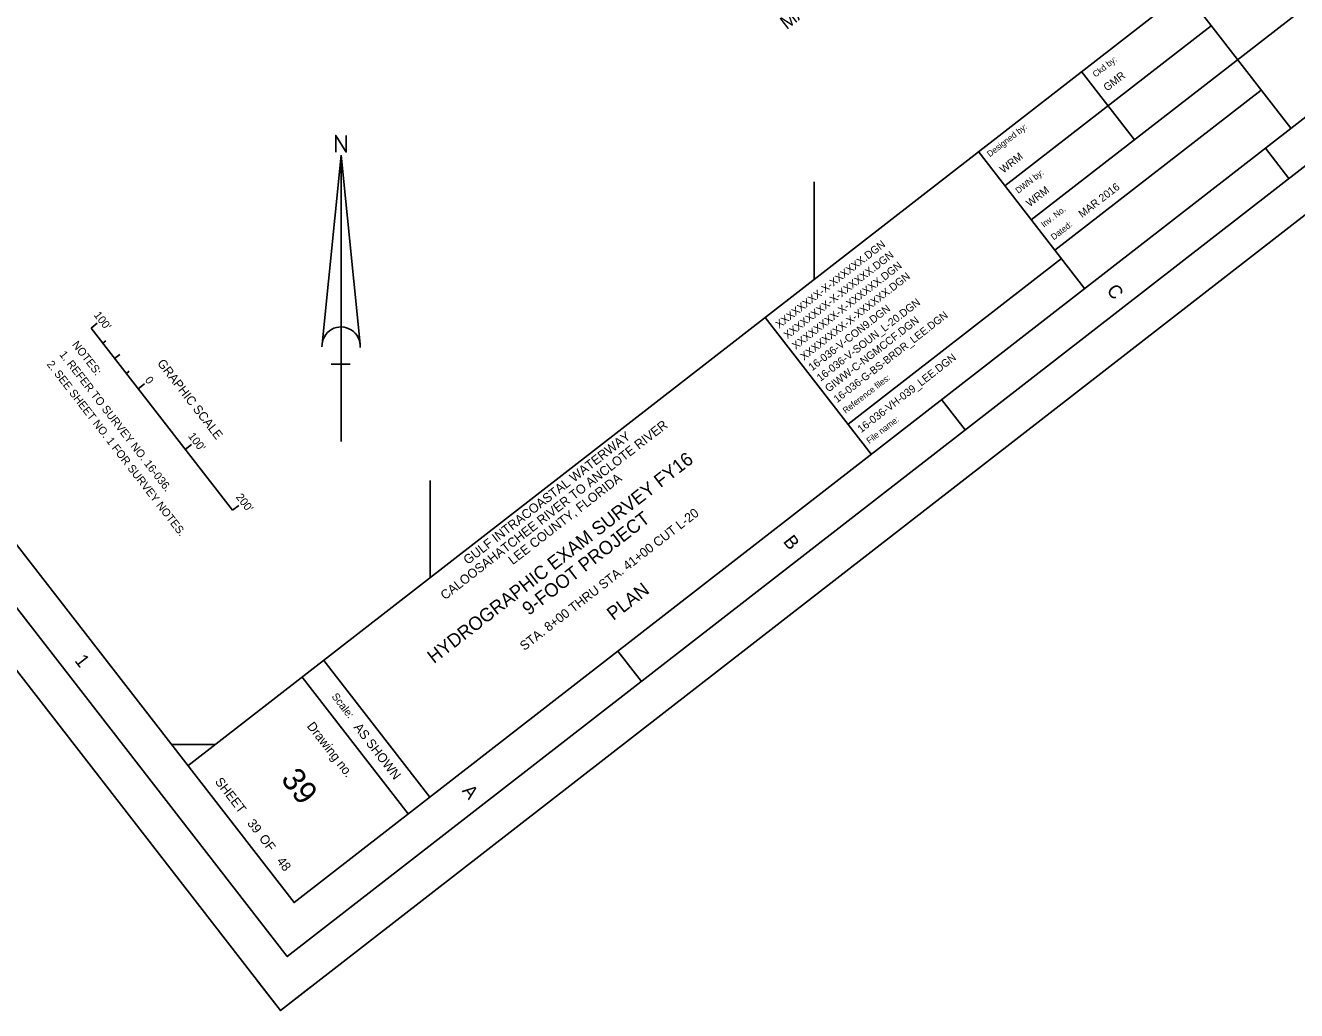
# Model space of a CAD drawing. Extents: x 577607 to 582991, y 855154 to 860715.
# Drawn here: x 579974 to 581627, y 855154 to 856435 of the extents above; entities that cross this region are included whole.
import ezdxf

# ---------------------------------------------------------------- set-up
doc = ezdxf.new("R2010")
doc.units = 0
for name, color, linetype in [('G-ANNO-NPLT', 7, 'Continuous'), ('G-ANNO-TEXT-DRWG', 7, 'Continuous'), ('G-ANNO-TEXT-PROJ', 7, 'Continuous'), ('G-ANNO-TEXT-TTLB', 7, 'Continuous'), ('G-ANNO-TTLB', 7, 'Continuous'), ('V-ANNO-MATC-IDEN', 7, 'Continuous'), ('V-ANNO-NOTE', 7, 'Continuous'), ('V-ANNO-SYMB', 7, 'Continuous'), ('V-TOPO-COOR-STAT', 7, 'Continuous')]:
    doc.layers.add(name, color=color, linetype=linetype)

msp = doc.modelspace()

# ---------------------------------------------------------------- linework, layer by layer
at = {"layer": 'G-ANNO-NPLT'}
msp.add_lwpolyline([(580293.3, 860714.9), (582991.2, 857239.1), (580305.4, 855154.4), (577607.4, 858630.1)], close=True, dxfattribs=at)
msp.add_lwpolyline([(580345, 855184.9), (580305.5, 855154.3), (580274.8, 855193.8)], dxfattribs=at)
at = {"layer": 'G-ANNO-TTLB'}
for p, q in [((582712.9, 857434.6), (580185.1, 855472.4)), ((581282.3, 856182.5), (581961.7, 856709)), ((581481.6, 856479.8), (581620, 856301.4)), ((581248, 856226.7), (581516.5, 856434.8)), ((581347.4, 856375.6), (581416.5, 856286.5)), ((581581.4, 856351.1), (581313.1, 856142.9)), ((581617.5, 856236.2), (581586.9, 856275.7)), ((581213, 856271.8), (581351.7, 856093.1)), ((581321.5, 856132.1), (581043.9, 855916.6)), ((580936.1, 856055.4), (581074.1, 855877.7)), ((581196.3, 855909.2), (581165.6, 855948.7)), ((580775, 855582.2), (580744.3, 855621.7)), ((580361.8, 855609.6), (580499.8, 855431.9)), ((580333.6, 855587.8), (580471.6, 855410))]:
    msp.add_line(p, q, dxfattribs=at)
for points in [[(577677.6, 858621.3), (580314.2, 855224.5), (582921, 857248), (580284.4, 860644.7)], [(582850.9, 857256.8), (580321.6, 860515.3), (577793.7, 858553.2), (580323.1, 855294.7)]]:
    msp.add_lwpolyline(points, close=True, dxfattribs=at)
at = {"layer": 'V-ANNO-NOTE'}
for p, q in [((580058.9, 856041.7), (580067.1, 856048.1)), ((580058.9, 856041.7), (580242.8, 855804.7)), ((580074.2, 856021.9), (580078, 856024.9)), ((580089.5, 856002.2), (580096.3, 856007.4)), ((580104.9, 855982.4), (580108.6, 855985.4)), ((580120.2, 855962.7), (580128.4, 855969.1)), ((580120.2, 855962.7), (580128.4, 855969.1)), ((580120.2, 855962.7), (580124.1, 855965.7)), ((580181.5, 855883.7), (580189.8, 855890.1)), ((580242.8, 855804.7), (580251.1, 855811.1))]:
    msp.add_line(p, q, dxfattribs=at)
at = {"layer": 'V-ANNO-SYMB'}
for p, q in [((580359.6, 856020.8), (580384.2, 856266.5)), ((580384.2, 855894.2), (580384.2, 856266.5)), ((580408.9, 856020.8), (580384.2, 856266.5)), ((580396, 855994.7), (580371.2, 855994.7))]:
    msp.add_line(p, q, dxfattribs=at)
msp.add_lwpolyline([(580377.4, 856270.5), (580377.4, 856292.2), (580390.9, 856270.5), (580390.9, 856292.2)], dxfattribs=at)
msp.add_arc((580384.2, 856018.3), 24.8, 355.2984, 182.0673, dxfattribs=at)
at = {"layer": 'V-TOPO-COOR-STAT'}
for p, q in [((581000, 856105), (581000, 856231.6)), ((580500, 855716.9), (580500, 855843.5)), ((580163.7, 855500), (580220.6, 855500))]:
    msp.add_line(p, q, dxfattribs=at)

# ---------------------------------------------------------------- texts
at = {"layer": 'G-ANNO-TEXT-DRWG'}
for s, height, rotation, p in [('GMR', 10, 37.8192, (581381, 856349.1)), ('WRM', 10, 37.8192, (581246, 856242.4)), ('WRM', 10, 37.8192, (581280.3, 856198.6)), ('XXXXXXXX-X-XXXXXX.DGN', 10, 37.8192, (580954.3, 856040.7)), ('XXXXXXXX-X-XXXXXX.DGN', 10, 37.8192, (580965.1, 856026.9)), ('XXXXXXXX-X-XXXXXX.DGN', 10, 37.8192, (580975.8, 856013.1)), ('XXXXXXXX-X-XXXXXX.DGN', 10, 37.8192, (580986.5, 855999.2)), ('16-036-V-SOUN_L-20.DGN', 10, 37.8192, (581008, 855971.6)), ('16-036-V-CON9.DGN', 10, 37.8192, (580997.2, 855985.4)), ('GIWW-C-NGMCCF.DGN', 10, 37.8192, (581018.7, 855957.8)), ('16-036-VH-039_LEE.DGN', 10, 37.8192, (581061, 855904.9)), ('STA. 8+00 THRU STA. 41+00 CUT L-20', 12, 37.8192, (580622.7, 855621.7)), ('PLAN', 17.5, 37.8192, (580738.6, 855660.8)), ('39', 30, 307.8192, (580304.9, 855454.8)), (' 39          48', 12, 307.8192, (580258.8, 855401.1))]:
    msp.add_text(s, height=height, rotation=rotation, dxfattribs=at).set_placement(p)
at = {"layer": 'G-ANNO-TEXT-PROJ'}
for s, height, p in [('MAR 2016', 10, (581348.5, 856184.6)), ('16-036-G-BS-BRDR_LEE.DGN', 9.8, (581029.8, 855944)), ('CALOOSAHATCHEE RIVER TO ANCLOTE RIVER', 12, (580519.5, 855687.6)), ('GULF INTRACOASTAL WATERWAY', 12, (580549.2, 855733.5)), ('HYDROGRAPHIC EXAM SURVEY FY16', 17.5, (580505.1, 855604.7)), ('LEE COUNTY, FLORIDA', 12, (580607.7, 855733.3)), ('9-FOOT PROJECT', 17.5, (580628.5, 855667.2))]:
    msp.add_text(s, height=height, rotation=37.8192, dxfattribs=at).set_placement(p)
at = {"layer": 'G-ANNO-TEXT-TTLB'}
for s, height, rotation, p in [('Ckd by:', 8, 37.8192, (581365.9, 856367.2)), ('Designed by:', 8, 37.8192, (581228.5, 856263.6)), ('DWN by:', 8, 37.8192, (581265.5, 856216.1)), ('Inv. No.', 8, 37.8192, (581298.8, 856172)), ('Dated:', 8, 37.8192, (581311.6, 856155.6)), ('Reference files:', 8, 37.8192, (581040.8, 855930.1)), ('File name:', 8, 37.8192, (581071.6, 855890.8)), ('Scale:', 10, 307.8192, (580371.4, 855562.5)), ('Drawing no.', 12, 307.8192, (580339.2, 855523.9)), ('AS SHOWN', 12, 307.8192, (580400.1, 855522.3)), ('SHEET         OF', 12, 307.8192, (580219.5, 855451.7))]:
    msp.add_text(s, height=height, rotation=rotation, dxfattribs=at).set_placement(p)
at = {"layer": 'G-ANNO-TTLB'}
for s, p in [('C', (581379.5, 856090.4)), ('B', (580958.7, 855764)), ('1', (580036.8, 855609.1)), ('A', (580541, 855439.8))]:
    msp.add_text(s, height=17.5, rotation=307.8192, dxfattribs=at).set_placement(p)
at = {"layer": 'V-ANNO-MATC-IDEN'}
msp.add_text('MATCHLINE SHEET NO. 038 LEE STA. 8+00', height=17.52, rotation=37.8192, dxfattribs=at).set_placement((580964, 856429.1))
at = {"layer": 'V-ANNO-NOTE'}
for s, height, p in [("100'", 10.42, (580062, 856058.4)), ('1. REFER TO SURVEY NO. 16-036.', 10.416, (580017.2, 856007.1)), ('NOTES:', 10.42, (580033.7, 856019.9)), ('2. SEE SHEET NO. 1 FOR SURVEY NOTES.', 10.416, (580000.8, 855994.4)), ('GRAPHIC SCALE', 11.666, (580144.5, 855995.7)), ('0', 10.4, (580128.5, 855973.8)), ("100'", 10.42, (580184.7, 855900.9)), ("200'", 10.42, (580246.8, 855821.8))]:
    msp.add_text(s, height=height, rotation=307.8192, dxfattribs=at).set_placement(p)

doc.saveas('drawing.dxf')
